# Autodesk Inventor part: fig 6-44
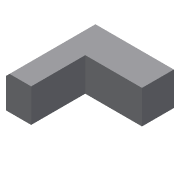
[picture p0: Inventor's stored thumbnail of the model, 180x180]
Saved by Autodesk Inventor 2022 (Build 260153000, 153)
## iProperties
Created: 2010-08
Part Number: fig 6-44
Document SubType Name: Modeling
Designer: CADSoft
Density: 1 g/cm^3
Material: Generic
Appearance: Default
Author: CADSoft
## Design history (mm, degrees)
sketch "Sketch1"
  geometry: L1 (-33.983, 0)-(-48.97, 0); L2 (-48.97, 0)-(-48.97, 51.503); L3 (-48.97, 51.503)-(0, 51.503); L4 (0, 51.503)-(0, 32.411); L5 (-33.983, 0)-(-33.983, 32.411); L6 (-33.983, 32.411)-(0, 32.411); 1 further point
  constraints: 12 end point, 3 parallel, 2 perpendicular, 1 horizontal
extrude "Extrusion1" new body sketch "Sketch1" distance "d0" = 20; taper "d1" = 0 deg
chamfer "Chamfer1" distance "d2" = 2; stored, may be unused: second distance "d3" = 2, angle "d4" = 45 deg
body "Solid1"
